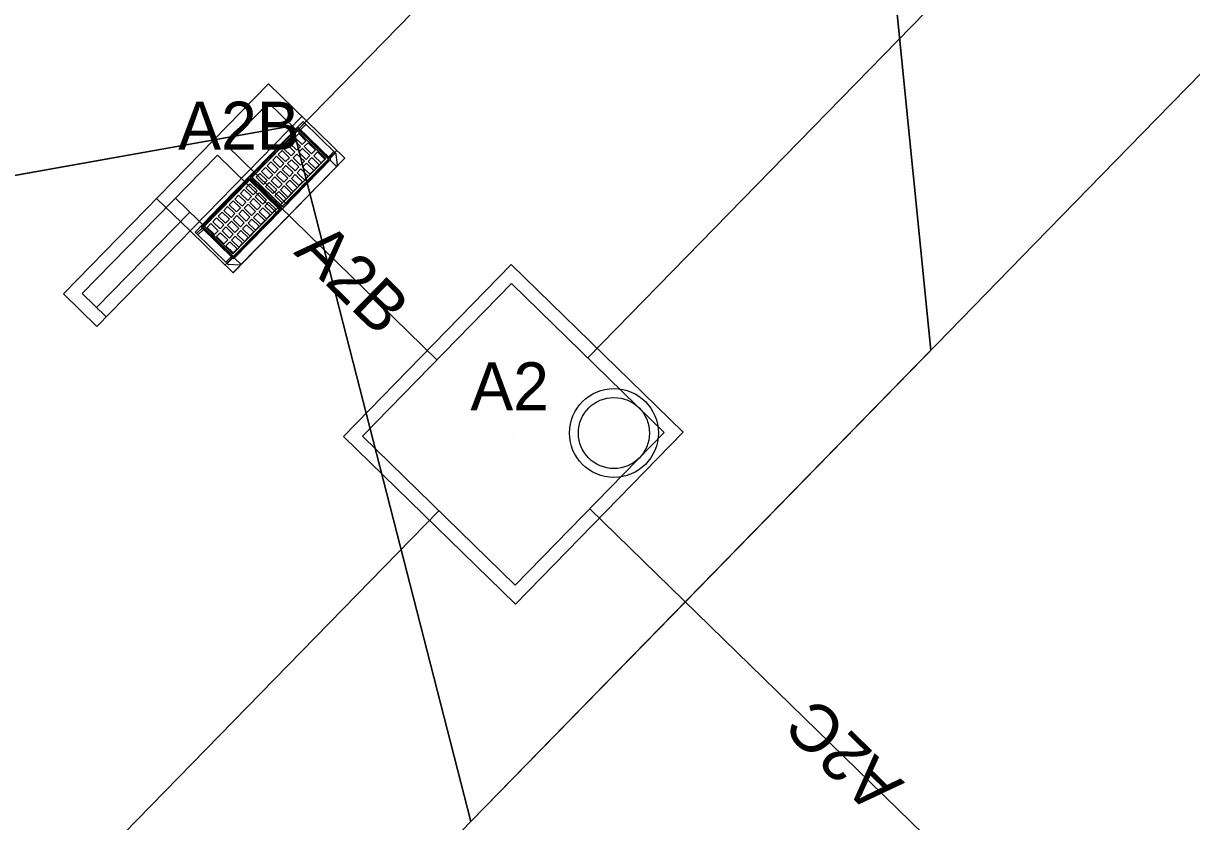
# Model space of a CAD drawing. Extents: x 2252703 to 2264864, y 13787568 to 13790989.
# Drawn here: x 2254857.99 to 2254901.78, y 13790752.9 to 13790782.84 of the extents above; entities that cross this region are included whole.
import ezdxf

# ---------------------------------------------------------------- set-up
doc = ezdxf.new("R2010")
doc.units = 0
for name, color, linetype in [('D_BOXES_1', 7, 'Continuous'), ('D_DRAIN_MISC', 7, 'Continuous'), ('D_DRAIN_NOTES_1', 7, 'Continuous'), ('D_DRN_AREA_X', 7, 'Continuous'), ('D_INLET_1', 7, 'Continuous'), ('D_PIPES_1', 7, 'Continuous')]:
    doc.layers.add(name, color=color, linetype=linetype)

msp = doc.modelspace()

# ---------------------------------------------------------------- linework, layer by layer
at = {"layer": 'D_BOXES_1'}
for p, q in [((2254879.145, 13790770.287), (2254992.252, 13790886.265)), ((2254701.107, 13790587.73), (2254873.56, 13790764.56))]:
    msp.add_line(p, q, dxfattribs=at)
at = {"layer": 'D_DRAIN_MISC'}
for p, q in [((2254868.254, 13790778.813), (2254868.254, 13790778.813)), ((2254865.435, 13790778.071), (2254865.435, 13790778.071)), ((2254866.33, 13790777.198), (2254866.33, 13790777.198)), ((2254867.583, 13790775.976), (2254867.583, 13790775.976)), ((2254864.763, 13790775.234), (2254864.763, 13790775.234)), ((2254879.145, 13790770.287), (2254879.145, 13790770.287)), ((2254873.489, 13790770.216), (2254873.489, 13790770.216)), ((2254876.353, 13790767.423), (2254876.353, 13790767.423)), ((2254879.216, 13790764.631), (2254879.216, 13790764.631)), ((2254873.56, 13790764.56), (2254873.56, 13790764.56))]:
    msp.add_line(p, q, dxfattribs=at)
at = {"layer": 'D_DRN_AREA_X'}
for p, q in [((2254900.446, 13790779.238), (2254993.845, 13790875.008)), ((2254992.751, 13790873.885), (2254900.446, 13790779.238)), ((2254889.021, 13790800.465), (2254891.998, 13790770.575)), ((2254891.998, 13790770.575), (2254889.021, 13790800.465)), ((2254895.904, 13790774.58), (2254900.446, 13790779.238)), ((2254900.446, 13790779.238), (2254895.904, 13790774.58)), ((2254868.081, 13790778.994), (2254856.243, 13790776.881)), ((2254856.243, 13790776.881), (2254868.081, 13790778.994)), ((2254874.758, 13790752.898), (2254868.081, 13790778.994)), ((2254868.081, 13790778.994), (2254874.758, 13790752.898)), ((2254892.224, 13790770.808), (2254895.904, 13790774.58)), ((2254895.904, 13790774.58), (2254892.224, 13790770.808)), ((2254892.224, 13790770.808), (2254881.752, 13790760.069)), ((2254891.998, 13790770.575), (2254892.224, 13790770.808)), ((2254874.758, 13790752.898), (2254891.998, 13790770.575)), ((2254881.752, 13790760.069), (2254874.758, 13790752.898)), ((2254832.878, 13790709.955), (2254874.758, 13790752.898))]:
    msp.add_line(p, q, dxfattribs=at)
at = {"layer": 'D_INLET_1'}
for p, q in [((2254867.171, 13790780.568), (2254859.491, 13790772.693)), ((2254870.035, 13790777.775), (2254867.171, 13790780.568)), ((2254867.18, 13790779.861), (2254865.609, 13790778.25)), ((2254869.328, 13790777.766), (2254867.18, 13790779.861)), ((2254868.424, 13790779.346), (2254860.744, 13790771.471)), ((2254868.473, 13790779.16), (2254865.381, 13790775.989)), ((2254868.328, 13790778.892), (2254868.532, 13790779.101)), ((2254868.379, 13790778.842), (2254868.583, 13790779.052)), ((2254869.702, 13790777.961), (2254868.473, 13790779.16)), ((2254868.294, 13790778.925), (2254866.488, 13790777.073)), ((2254868.299, 13790778.862), (2254866.551, 13790777.07)), ((2254868.297, 13790778.843), (2254866.57, 13790777.073)), ((2254868.308, 13790778.701), (2254868.166, 13790778.555)), ((2254869.512, 13790777.738), (2254868.294, 13790778.925)), ((2254869.429, 13790777.738), (2254868.297, 13790778.843)), ((2254869.449, 13790777.741), (2254868.299, 13790778.862)), ((2254868.582, 13790778.433), (2254868.308, 13790778.701)), ((2254865.609, 13790778.25), (2254867.814, 13790776.099)), ((2254867.893, 13790778.275), (2254867.751, 13790778.13)), ((2254867.893, 13790778.275), (2254868.167, 13790778.007)), ((2254868.1, 13790778.488), (2254867.958, 13790778.342)), ((2254867.958, 13790778.342), (2254868.233, 13790778.075)), ((2254868.1, 13790778.488), (2254868.375, 13790778.22)), ((2254868.166, 13790778.555), (2254868.44, 13790778.287)), ((2254868.233, 13790778.075), (2254868.375, 13790778.22)), ((2254868.44, 13790778.287), (2254868.582, 13790778.433)), ((2254868.517, 13790778.213), (2254868.659, 13790778.358)), ((2254868.517, 13790778.213), (2254868.794, 13790777.943)), ((2254868.936, 13790778.088), (2254868.659, 13790778.358)), ((2254865.26, 13790777.892), (2254860.198, 13790772.701)), ((2254865.26, 13790777.892), (2254867.465, 13790775.741)), ((2254869.734, 13790778.068), (2254865.545, 13790773.773)), ((2254869.328, 13790777.766), (2254865.837, 13790774.186)), ((2254870.032, 13790777.778), (2254865.843, 13790773.482)), ((2254870.035, 13790777.775), (2254865.846, 13790773.479)), ((2254867.477, 13790777.849), (2254867.335, 13790777.704)), ((2254867.477, 13790777.849), (2254867.752, 13790777.582)), ((2254867.685, 13790778.062), (2254867.543, 13790777.917)), ((2254867.543, 13790777.917), (2254867.818, 13790777.649)), ((2254867.685, 13790778.062), (2254867.96, 13790777.794)), ((2254869.449, 13790777.741), (2254867.7, 13790775.949)), ((2254867.703, 13790775.968), (2254869.429, 13790777.738)), ((2254869.512, 13790777.738), (2254867.705, 13790775.886)), ((2254867.751, 13790778.13), (2254868.025, 13790777.862)), ((2254867.818, 13790777.649), (2254867.96, 13790777.794)), ((2254867.894, 13790777.574), (2254868.036, 13790777.72)), ((2254868.025, 13790777.862), (2254868.167, 13790778.007)), ((2254868.036, 13790777.72), (2254868.313, 13790777.45)), ((2254868.102, 13790777.787), (2254868.244, 13790777.933)), ((2254868.102, 13790777.787), (2254868.379, 13790777.517)), ((2254868.244, 13790777.933), (2254868.521, 13790777.663)), ((2254868.309, 13790778), (2254868.451, 13790778.145)), ((2254868.309, 13790778), (2254868.586, 13790777.73)), ((2254868.451, 13790778.145), (2254868.728, 13790777.876)), ((2254868.586, 13790777.73), (2254868.728, 13790777.876)), ((2254868.663, 13790777.655), (2254868.805, 13790777.801)), ((2254868.794, 13790777.943), (2254868.936, 13790778.088)), ((2254868.805, 13790777.801), (2254869.079, 13790777.533)), ((2254868.87, 13790777.868), (2254869.012, 13790778.014)), ((2254868.87, 13790777.868), (2254869.145, 13790777.6)), ((2254869.287, 13790777.746), (2254869.012, 13790778.014)), ((2254869.145, 13790777.6), (2254869.287, 13790777.746)), ((2254869.427, 13790777.821), (2254869.631, 13790778.03)), ((2254869.478, 13790777.771), (2254869.682, 13790777.98)), ((2254869.757, 13790777.516), (2254869.718, 13790777.929)), ((2254869.746, 13790777.484), (2254866.129, 13790773.775)), ((2254867.062, 13790777.424), (2254866.92, 13790777.278)), ((2254866.92, 13790777.278), (2254867.195, 13790777.01)), ((2254867.062, 13790777.424), (2254867.337, 13790777.156)), ((2254867.27, 13790777.637), (2254867.128, 13790777.491)), ((2254867.128, 13790777.491), (2254867.402, 13790777.223)), ((2254867.27, 13790777.637), (2254867.544, 13790777.369)), ((2254867.335, 13790777.704), (2254867.61, 13790777.436)), ((2254867.402, 13790777.223), (2254867.544, 13790777.369)), ((2254867.479, 13790777.148), (2254867.621, 13790777.294)), ((2254867.61, 13790777.436), (2254867.752, 13790777.582)), ((2254867.621, 13790777.294), (2254867.898, 13790777.024)), ((2254867.687, 13790777.361), (2254867.829, 13790777.507)), ((2254867.687, 13790777.361), (2254867.963, 13790777.091)), ((2254867.829, 13790777.507), (2254868.105, 13790777.237)), ((2254869.417, 13790777.685), (2254867.843, 13790776.072)), ((2254867.894, 13790777.574), (2254868.171, 13790777.304)), ((2254868.171, 13790777.304), (2254868.313, 13790777.45)), ((2254868.248, 13790777.229), (2254868.39, 13790777.375)), ((2254868.379, 13790777.517), (2254868.521, 13790777.663)), ((2254868.39, 13790777.375), (2254868.664, 13790777.107)), ((2254868.455, 13790777.442), (2254868.597, 13790777.588)), ((2254868.455, 13790777.442), (2254868.73, 13790777.175)), ((2254868.597, 13790777.588), (2254868.872, 13790777.32)), ((2254868.663, 13790777.655), (2254868.937, 13790777.387)), ((2254868.73, 13790777.175), (2254868.872, 13790777.32)), ((2254868.937, 13790777.387), (2254869.079, 13790777.533)), ((2254869.483, 13790777.708), (2254869.73, 13790777.467)), ((2254864.652, 13790775.191), (2254866.459, 13790777.043)), ((2254864.715, 13790775.188), (2254866.464, 13790776.98)), ((2254864.735, 13790775.19), (2254866.461, 13790776.961)), ((2254867.676, 13790775.856), (2254866.459, 13790777.043)), ((2254867.594, 13790775.856), (2254866.461, 13790776.961)), ((2254867.613, 13790775.859), (2254866.464, 13790776.98)), ((2254867.705, 13790775.886), (2254866.488, 13790777.073)), ((2254867.7, 13790775.949), (2254866.551, 13790777.07)), ((2254867.703, 13790775.968), (2254866.57, 13790777.073)), ((2254866.855, 13790777.211), (2254866.713, 13790777.065)), ((2254866.987, 13790776.797), (2254866.713, 13790777.065)), ((2254866.855, 13790777.211), (2254867.129, 13790776.943)), ((2254866.987, 13790776.797), (2254867.129, 13790776.943)), ((2254867.064, 13790776.723), (2254867.206, 13790776.868)), ((2254867.195, 13790777.01), (2254867.337, 13790777.156)), ((2254867.206, 13790776.868), (2254867.483, 13790776.598)), ((2254867.271, 13790776.935), (2254867.413, 13790777.081)), ((2254867.271, 13790776.935), (2254867.548, 13790776.666)), ((2254867.413, 13790777.081), (2254867.69, 13790776.811)), ((2254867.479, 13790777.148), (2254867.756, 13790776.878)), ((2254867.756, 13790776.878), (2254867.898, 13790777.024)), ((2254867.832, 13790776.804), (2254867.974, 13790776.949)), ((2254867.963, 13790777.091), (2254868.105, 13790777.237)), ((2254867.974, 13790776.949), (2254868.249, 13790776.682)), ((2254868.04, 13790777.017), (2254868.182, 13790777.162)), ((2254868.04, 13790777.017), (2254868.315, 13790776.749)), ((2254868.182, 13790777.162), (2254868.457, 13790776.894)), ((2254868.248, 13790777.229), (2254868.522, 13790776.962)), ((2254868.315, 13790776.749), (2254868.457, 13790776.894)), ((2254868.522, 13790776.962), (2254868.664, 13790777.107)), ((2254866.123, 13790776.46), (2254866.265, 13790776.606)), ((2254866.123, 13790776.46), (2254866.397, 13790776.192)), ((2254866.265, 13790776.606), (2254866.539, 13790776.338)), ((2254866.33, 13790776.673), (2254866.472, 13790776.819)), ((2254866.33, 13790776.673), (2254866.605, 13790776.405)), ((2254866.747, 13790776.551), (2254866.472, 13790776.819)), ((2254866.747, 13790776.551), (2254866.605, 13790776.405)), ((2254866.823, 13790776.476), (2254866.681, 13790776.331)), ((2254867.1, 13790776.206), (2254866.823, 13790776.476)), ((2254867.341, 13790776.453), (2254867.064, 13790776.723)), ((2254867.341, 13790776.453), (2254867.483, 13790776.598)), ((2254867.417, 13790776.378), (2254867.559, 13790776.524)), ((2254867.548, 13790776.666), (2254867.69, 13790776.811)), ((2254867.559, 13790776.524), (2254867.834, 13790776.256)), ((2254867.625, 13790776.591), (2254867.767, 13790776.737)), ((2254867.625, 13790776.591), (2254867.899, 13790776.323)), ((2254867.767, 13790776.737), (2254868.041, 13790776.469)), ((2254867.832, 13790776.804), (2254868.107, 13790776.536)), ((2254867.899, 13790776.323), (2254868.041, 13790776.469)), ((2254868.107, 13790776.536), (2254868.249, 13790776.682)), ((2254864.235, 13790775.05), (2254862.982, 13790776.272)), ((2254865.837, 13790774.186), (2254863.689, 13790776.281)), ((2254865.381, 13790775.989), (2254864.423, 13790775.007)), ((2254865.5, 13790775.822), (2254865.642, 13790775.967)), ((2254865.642, 13790775.967), (2254865.916, 13790775.699)), ((2254865.707, 13790776.034), (2254865.849, 13790776.18)), ((2254865.707, 13790776.034), (2254865.982, 13790775.767)), ((2254865.849, 13790776.18), (2254866.124, 13790775.912)), ((2254865.915, 13790776.247), (2254866.057, 13790776.393)), ((2254865.915, 13790776.247), (2254866.19, 13790775.979)), ((2254866.057, 13790776.393), (2254866.332, 13790776.125)), ((2254866.332, 13790776.125), (2254866.19, 13790775.979)), ((2254866.408, 13790776.05), (2254866.266, 13790775.905)), ((2254866.539, 13790776.338), (2254866.397, 13790776.192)), ((2254866.408, 13790776.05), (2254866.685, 13790775.781)), ((2254866.616, 13790776.263), (2254866.474, 13790776.118)), ((2254866.474, 13790776.118), (2254866.75, 13790775.848)), ((2254866.616, 13790776.263), (2254866.893, 13790775.993)), ((2254866.681, 13790776.331), (2254866.958, 13790776.061)), ((2254866.893, 13790775.993), (2254866.75, 13790775.848)), ((2254867.1, 13790776.206), (2254866.958, 13790776.061)), ((2254867.177, 13790776.132), (2254867.035, 13790775.986)), ((2254867.035, 13790775.986), (2254867.309, 13790775.718)), ((2254867.451, 13790775.864), (2254867.177, 13790776.132)), ((2254867.692, 13790776.11), (2254867.417, 13790776.378)), ((2254867.692, 13790776.11), (2254867.834, 13790776.256)), ((2254864.226, 13790775.757), (2254860.735, 13790772.178)), ((2254865.085, 13790775.396), (2254865.227, 13790775.541)), ((2254865.227, 13790775.541), (2254865.501, 13790775.274)), ((2254865.292, 13790775.609), (2254865.434, 13790775.754)), ((2254865.292, 13790775.609), (2254865.567, 13790775.341)), ((2254865.434, 13790775.754), (2254865.709, 13790775.487)), ((2254865.5, 13790775.822), (2254865.774, 13790775.554)), ((2254865.916, 13790775.699), (2254865.774, 13790775.554)), ((2254865.993, 13790775.625), (2254865.851, 13790775.479)), ((2254865.865, 13790774.067), (2254867.613, 13790775.859)), ((2254867.594, 13790775.856), (2254865.867, 13790774.086)), ((2254865.87, 13790774.003), (2254867.676, 13790775.856)), ((2254867.494, 13790775.713), (2254865.92, 13790774.1)), ((2254866.124, 13790775.912), (2254865.982, 13790775.767)), ((2254865.993, 13790775.625), (2254866.27, 13790775.355)), ((2254866.201, 13790775.838), (2254866.059, 13790775.692)), ((2254866.059, 13790775.692), (2254866.335, 13790775.422)), ((2254866.201, 13790775.838), (2254866.477, 13790775.568)), ((2254866.266, 13790775.905), (2254866.543, 13790775.635)), ((2254866.477, 13790775.568), (2254866.335, 13790775.422)), ((2254866.685, 13790775.781), (2254866.543, 13790775.635)), ((2254866.762, 13790775.706), (2254866.62, 13790775.56)), ((2254866.62, 13790775.56), (2254866.894, 13790775.292)), ((2254866.762, 13790775.706), (2254867.036, 13790775.438)), ((2254866.969, 13790775.919), (2254866.827, 13790775.773)), ((2254866.827, 13790775.773), (2254867.102, 13790775.505)), ((2254866.969, 13790775.919), (2254867.244, 13790775.651)), ((2254867.244, 13790775.651), (2254867.102, 13790775.505)), ((2254867.451, 13790775.864), (2254867.309, 13790775.718)), ((2254864.686, 13790775.158), (2254864.482, 13790774.949)), ((2254864.737, 13790775.108), (2254864.533, 13790774.899)), ((2254865.87, 13790774.003), (2254864.652, 13790775.191)), ((2254865.865, 13790774.067), (2254864.715, 13790775.188)), ((2254865.867, 13790774.086), (2254864.735, 13790775.19)), ((2254864.877, 13790775.183), (2254865.019, 13790775.329)), ((2254865.152, 13790774.915), (2254864.877, 13790775.183)), ((2254865.019, 13790775.329), (2254865.294, 13790775.061)), ((2254865.085, 13790775.396), (2254865.359, 13790775.128)), ((2254865.501, 13790775.274), (2254865.359, 13790775.128)), ((2254865.578, 13790775.199), (2254865.436, 13790775.053)), ((2254865.709, 13790775.487), (2254865.567, 13790775.341)), ((2254865.578, 13790775.199), (2254865.855, 13790774.929)), ((2254865.785, 13790775.412), (2254865.643, 13790775.266)), ((2254865.643, 13790775.266), (2254865.92, 13790774.996)), ((2254865.785, 13790775.412), (2254866.062, 13790775.142)), ((2254865.851, 13790775.479), (2254866.128, 13790775.209)), ((2254866.062, 13790775.142), (2254865.92, 13790774.996)), ((2254866.27, 13790775.355), (2254866.128, 13790775.209)), ((2254866.346, 13790775.28), (2254866.204, 13790775.134)), ((2254866.204, 13790775.134), (2254866.479, 13790774.867)), ((2254866.346, 13790775.28), (2254866.621, 13790775.012)), ((2254866.554, 13790775.493), (2254866.412, 13790775.347)), ((2254866.412, 13790775.347), (2254866.687, 13790775.079)), ((2254866.554, 13790775.493), (2254866.829, 13790775.225)), ((2254866.829, 13790775.225), (2254866.687, 13790775.079)), ((2254867.036, 13790775.438), (2254866.894, 13790775.292)), ((2254865.846, 13790773.479), (2254864.235, 13790775.05)), ((2254865.652, 13790773.808), (2254864.423, 13790775.007)), ((2254865.294, 13790775.061), (2254865.152, 13790774.915)), ((2254865.37, 13790774.986), (2254865.228, 13790774.84)), ((2254865.505, 13790774.571), (2254865.228, 13790774.84)), ((2254865.37, 13790774.986), (2254865.647, 13790774.716)), ((2254865.436, 13790775.053), (2254865.712, 13790774.783)), ((2254865.647, 13790774.716), (2254865.505, 13790774.571)), ((2254865.855, 13790774.929), (2254865.712, 13790774.783)), ((2254865.931, 13790774.854), (2254865.789, 13790774.709)), ((2254865.789, 13790774.709), (2254866.064, 13790774.441)), ((2254865.931, 13790774.854), (2254866.206, 13790774.587)), ((2254866.139, 13790775.067), (2254865.997, 13790774.922)), ((2254865.997, 13790774.922), (2254866.271, 13790774.654)), ((2254866.139, 13790775.067), (2254866.413, 13790774.799)), ((2254866.413, 13790774.799), (2254866.271, 13790774.654)), ((2254866.621, 13790775.012), (2254866.479, 13790774.867)), ((2254865.724, 13790774.641), (2254865.582, 13790774.496)), ((2254865.856, 13790774.228), (2254865.582, 13790774.496)), ((2254865.724, 13790774.641), (2254865.998, 13790774.374)), ((2254865.998, 13790774.374), (2254865.856, 13790774.228)), ((2254866.206, 13790774.587), (2254866.064, 13790774.441)), ((2254865.785, 13790774.086), (2254865.581, 13790773.877)), ((2254865.836, 13790774.037), (2254865.632, 13790773.828)), ((2254866.098, 13790773.764), (2254865.684, 13790773.793)), ((2254865.899, 13790774.033), (2254866.146, 13790773.792)), ((2254869.989, 13790767.344), (2254876.273, 13790773.787)), ((2254876.273, 13790773.787), (2254882.716, 13790767.503)), ((2254870.696, 13790767.352), (2254876.282, 13790773.08)), ((2254876.282, 13790773.08), (2254882.009, 13790767.494)), ((2254859.491, 13790772.693), (2254860.744, 13790771.471)), ((2254860.198, 13790772.701), (2254861.093, 13790771.829)), ((2254876.432, 13790761.06), (2254869.989, 13790767.344)), ((2254876.423, 13790761.767), (2254870.696, 13790767.352)), ((2254882.009, 13790767.494), (2254876.423, 13790761.767)), ((2254882.716, 13790767.503), (2254876.432, 13790761.06))]:
    msp.add_line(p, q, dxfattribs=at)
for radius in [1.666, 1.333]:
    msp.add_circle((2254880.124, 13790767.471), radius, dxfattribs=at)
for centre, start_param, end_param in [((2254869.673, 13790777.931), 0.80294, 1.570796), ((2254869.712, 13790777.518), 0, 0.80294), ((2254865.681, 13790773.838), 4.712389, 5.480245), ((2254866.095, 13790773.809), 5.480245, 6.283185)]:
    msp.add_ellipse(centre, major_axis=(0.0341, -0.0332), ratio=0.877193, start_param=start_param, end_param=end_param, dxfattribs=at)
at = {"layer": 'D_PIPES_1'}
for p, q in [((2254882.218, 13790793.131), (2254868.254, 13790778.813)), ((2254867.583, 13790775.976), (2254873.489, 13790770.216)), ((2254898.009, 13790746.303), (2254879.216, 13790764.631))]:
    msp.add_line(p, q, dxfattribs=at)

# ---------------------------------------------------------------- texts
at = {"layer": 'D_DRAIN_NOTES_1'}
for s, p in [('A2B', (2254863.793, 13790778.098)), ('A2', (2254874.744, 13790768.323))]:
    msp.add_text(s, height=1.8, dxfattribs=at).set_placement(p)
for s, rotation, p in [('A2B', 315.7179, (2254868.092, 13790774.223)), ('A2C', 135.7179, (2254891.042, 13790754.355))]:
    msp.add_text(s, height=1.8, rotation=rotation, dxfattribs=at).set_placement(p)

doc.saveas('drawing.dxf')
